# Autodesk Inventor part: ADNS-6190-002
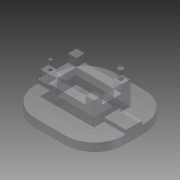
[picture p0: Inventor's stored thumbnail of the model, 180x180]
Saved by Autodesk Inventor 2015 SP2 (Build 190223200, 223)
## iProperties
Created: 2015-10
Part Number: ADNS-6190-002
Material: Polycarbonat, klar
Document SubType Name: Modeling
Designer: rYan
Mass: 1.11196 g
Surface Area: 12.3381 cm^2
Volume: 0.926633 cm^3
Density: 1.2 g/cm^3
Appearance: Polycarbonat - klar
Author: rYan
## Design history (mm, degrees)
sketch "Skizze1"
  geometry: L1 (-3.6, 9.5)-(3.6, 9.5); L2 (10.6, 2.5)-(10.6, -2.5); L3 (3.6, -9.5)-(-3.6, -9.5); L4 (-10.6, -2.5)-(-10.6, 2.5); L5 (0, 15.33)-(0, -15.33) reference; L6 (-16.87, 0)-(16.87, 0) reference; A1 r 7 centre (3.6, 2.5) between (10.6, 2.5) and (3.6, 9.5); A2 r 7 centre (3.6, -2.5) between (3.6, -9.5) and (10.6, -2.5); A3 r 7 centre (-3.6, -2.5) between (-10.6, -2.5) and (-3.6, -9.5); A4 r 7 centre (-3.6, 2.5) between (-3.6, 9.5) and (-10.6, 2.5); 4 further points
  constraints: 8 end point, 8 point on circle, 8 tangent, 6 point on line, 4 centre point, 3 equal radius, 2 parallel, 1 horizontal, 1 perpendicular, 2 other
  dimensions: "d0" = 21.2 distance of point (-10.6, 9.5) point (10.6, 9.5); "d1" = 19 distance of point (10.6, 9.5) point (10.6, -9.5); "d2" = 7 radius of A1
extrude "Extrusion1" new body sketch "Skizze1" distance "d3" = 1.9; taper "d4" = 0 deg
sketch "Skizze2"
  geometry: L1 (-7.6, 4.35)-(5.3, 4.35); L2 (5.3, 4.35)-(5.3, -4.35); L3 (5.3, -4.35)-(-7.6, -4.35); L4 (-7.6, -4.35)-(-7.6, 4.35); L5 (-14.84, 0)-(14.84, 0) reference; L6 (-10.6, 2.5)-(-10.6, -2.5) reference; 1 further point
  constraints: 8 end point, 2 parallel, 1 horizontal, 1 perpendicular, 1 other
  dimensions: "d5" = 8.7 distance of L1.end L2.end; "d6" = 12.9 distance of L1.start L1.end; "d7" = 3 distance between parallel lines of L4 L6
extrude "Extrusion2" join sketch "Skizze2" distance "d8" = 3.7; taper "d9" = 0 deg
feature "Wandung1" dims "d10" = 2
sketch "Skizze3"
  geometry: L1 (3.3, 2.35)-(3.3, -2.35) reference; L2 (3.3, -2.35)-(-5.6, -2.35) reference; L3 (-5.6, -2.35)-(-5.6, 2.35) reference; L4 (-5.6, 2.35)-(3.3, 2.35) reference; L5 (5.3, 4.35)-(-7.6, 4.35) reference; L6 (-7.6, 4.35)-(-7.6, -4.35) reference; L7 (-7.6, -4.35)-(5.3, -4.35) reference; L8 (5.3, -4.35)-(5.3, 4.35) reference; L9 (-7.6, 4.35)-(-5.6, 4.35); L10 (-5.6, 4.35)-(-5.6, 2.35); L11 (-5.6, 2.35)-(-7.6, 2.35); L12 (-7.6, 2.35)-(-7.6, 4.35); L13 (5.3, 4.35)-(3.3, 4.35); L14 (3.3, 4.35)-(3.3, 2.35); L15 (3.3, 2.35)-(5.3, 2.35); L16 (5.3, 2.35)-(5.3, 4.35); L17 (5.3, -4.35)-(3.3, -4.35); L18 (3.3, -4.35)-(3.3, -2.35); L19 (3.3, -2.35)-(5.3, -2.35); L20 (5.3, -2.35)-(5.3, -4.35); L21 (-7.6, -4.35)-(-5.6, -4.35); L22 (-5.6, -4.35)-(-5.6, -2.35); L23 (-5.6, -2.35)-(-7.6, -2.35); L24 (-7.6, -2.35)-(-7.6, -4.35); 1 further point
  constraints: 32 end point, 8 parallel, 4 horizontal, 4 perpendicular
extrude "Extrusion3" join sketch "Skizze3" distance "d11" = 1.9; taper "d12" = 0 deg
sketch "Skizze4"
  geometry: L1 (-14.84, 0)-(14.84, 0) reference; L2 (0, 13.3)-(0, -13.3) reference; C1 r 0.6 at (4, 3.35); C2 r 0.4 at (-6.29, -3.2); 1 further point
  constraints: 2 centre point
  dimensions: "d13" = 10.29 horizontal distance of C1.centre C2.centre; "d14" = 6.55 vertical distance of C2.centre C1.centre; "d15" = 3.35 distance from line of L1 C1.centre; "d16" = 4 distance from line of C1.centre L2; "d17" = 1.2 diameter of C1; "d18" = 0.8 diameter of C2
extrude "Extrusion4" join sketch "Skizze4" distance "d19" = 2.2; taper "d20" = 0 deg
sketch "Skizze5"
  geometry: L1 (5.3, 4.35)-(5.3, -4.35) reference; L2 (5.3, -4.35)-(-7.6, -4.35) reference; L3 (-7.6, -4.35)-(-7.6, 4.35) reference; L4 (-7.6, 4.35)-(5.3, 4.35) reference; L5 (3.6, 9.5)-(-3.6, 9.5) reference; L6 (-10.6, 2.5)-(-10.6, -2.5) reference; L7 (-3.6, -9.5)-(3.6, -9.5) reference; L8 (10.6, -2.5)-(10.6, 2.5) reference; L9 (-10.6, -2.5)-(-10.6, 2.5) reference; L10 (-7.6, 1.95)-(-10.6, 1.95); L11 (-10.6, 1.95)-(-10.6, -1.95); L12 (-10.6, -1.95)-(-7.6, -1.95); L13 (-7.6, -1.95)-(-7.6, 1.95); L14 (10.6, 2.5)-(10.6, -2.5) reference; L15 (5.3, 1.95)-(10.6, 1.95); L16 (10.6, 1.95)-(10.6, -1.95); L17 (10.6, -1.95)-(5.3, -1.95); L18 (5.3, -1.95)-(5.3, 1.95); L19 (-16.87, 0)-(16.87, 0) reference; A1 r 7 centre (-3.6, 2.5) between (-3.6, 9.5) and (-10.6, 2.5) reference; A2 r 7 centre (-3.6, -2.5) between (-10.6, -2.5) and (-3.6, -9.5) reference; A3 r 7 centre (3.6, -2.5) between (3.6, -9.5) and (10.6, -2.5) reference; A4 r 7 centre (3.6, 2.5) between (10.6, 2.5) and (3.6, 9.5) reference; 1 further point
  constraints: 16 end point, 6 point on line, 4 parallel, 2 horizontal, 2 perpendicular, 1 other
  dimensions: "d21" = 3.9 distance of L10.end L11.end
extrude "Extrusion5" join sketch "Skizze5" distance "d22" = 0.9; taper "d23" = 0 deg
sketch "Skizze6"
  geometry: L1 (3.6, 9.5)-(-3.6, 9.5) reference; L2 (-10.6, 2.5)-(-10.6, -2.5) reference; L3 (-3.6, -9.5)-(3.6, -9.5) reference; L4 (10.6, -2.5)-(10.6, 2.5) reference; L5 (3.6, -4.2)-(-3.6, -4.2); L6 (-5.3, -2.5)-(-5.3, 2.5); L7 (-3.6, 4.2)-(3.6, 4.2); L8 (5.3, 2.5)-(5.3, -2.5); A1 r 7 centre (-3.6, 2.5) between (-3.6, 9.5) and (-10.6, 2.5) reference; A2 r 7 centre (-3.6, -2.5) between (-10.6, -2.5) and (-3.6, -9.5) reference; A3 r 7 centre (3.6, -2.5) between (3.6, -9.5) and (10.6, -2.5) reference; A4 r 7 centre (3.6, 2.5) between (10.6, 2.5) and (3.6, 9.5) reference; A5 r 1.7 centre (3.6, -2.5) between (3.6, -4.2) and (5.3, -2.5); A6 r 1.7 centre (-3.6, -2.5) between (-5.3, -2.5) and (-3.6, -4.2); A7 r 1.7 centre (-3.6, 2.5) between (-3.6, 4.2) and (-5.3, 2.5); A8 r 1.7 centre (3.6, 2.5) between (5.3, 2.5) and (3.6, 4.2); 1 further point
  constraints: 8 end point, 8 point on circle, 4 centre point, 7 other
  dimensions: "d24" = 5.3 radial gap between concentric circles of A3 A5
extrude "Extrusion6" cut sketch "Skizze6" distance "d25" = 1; taper "d26" = 0 deg
node "Volumenkörper1"
node "Projizierte Kontur1"
node "Projizierte Kontur2"
node "Projizierte Kontur3"
